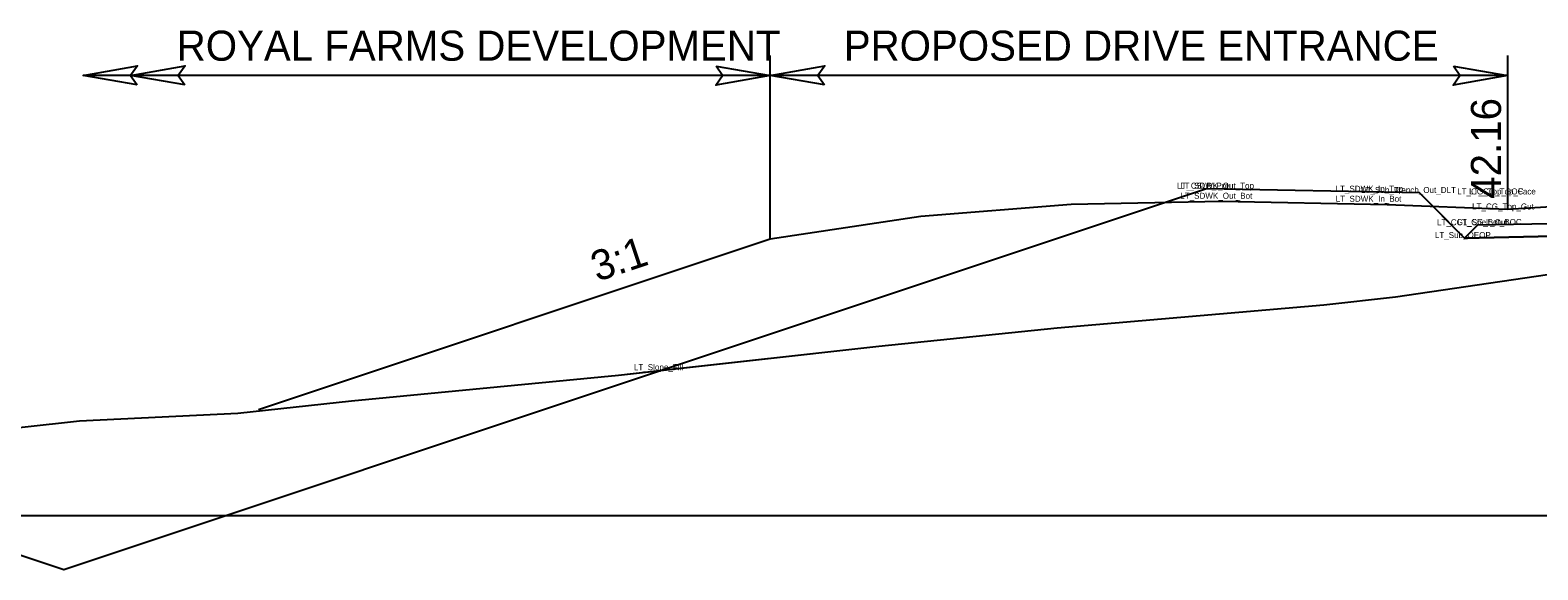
# Model space of a CAD drawing. Extents: x -26 to 2192773, y -11 to 86971.
# Drawn here: x 118.9 to 169, y 1998.2 to 2016.1 of the extents above; entities that cross this region are included whole.
import ezdxf

# ---------------------------------------------------------------- set-up
doc = ezdxf.new("R2010")
doc.units = 0
for name, color, linetype in [('Exist Cross Section Cell', 7, 'Continuous'), ('Exist XS Ground Line', 7, 'Continuous'), ('Old_Level_62', 7, 'Continuous'), ('Prop CMT Conc Surface', 7, 'Continuous'), ('Prop CMT Concrete Structures', 7, 'Continuous'), ('Prop CMT Pvmt Course 1 CG', 7, 'Continuous'), ('Prop CMT Slope Grass', 7, 'Continuous'), ('Prop CMT Subgrade Earthwork', 7, 'Continuous'), ('Prop Terminator CELL', 7, 'Continuous'), ('Prop XS Earthwork Shape', 7, 'Continuous'), ('Prop XS Hydro Elevations', 7, 'Continuous'), ('Prop XS Side Slope Text', 7, 'Continuous'), ('Scratch_Level_0', 7, 'Continuous')]:
    doc.layers.add(name, color=color, linetype=linetype)

msp = doc.modelspace()

# ---------------------------------------------------------------- linework, layer by layer
at = {"layer": 'Exist Cross Section Cell'}
msp.add_line((0, 2000), (200, 2000), dxfattribs=at)
at = {"layer": 'Exist XS Ground Line'}
msp.add_lwpolyline([(113.015, 2002.312), (120.545, 2003.136), (125.814, 2003.397), (129.587, 2003.806), (138.461, 2004.659), (147.108, 2005.62), (153.036, 2006.229), (161.901, 2006.996), (164.278, 2007.261), (171.291, 2008.285)], dxfattribs=at)
at = {"layer": 'Old_Level_62'}
for p, q in [((143.5, 2009.178), (143.5, 2015.27)), ((168, 2015.27), (168, 2010.158)), ((143.5, 2014.612), (120.668, 2014.612)), ((168, 2014.612), (143.5, 2014.612))]:
    msp.add_line(p, q, dxfattribs=at)
at = {"layer": 'Prop CMT Conc Surface'}
msp.add_lwpolyline([(170, 2010.278), (168, 2010.158)], dxfattribs=at)
at = {"layer": 'Prop CMT Concrete Structures'}
msp.add_lwpolyline([(170, 2010.278), (168, 2010.158)], dxfattribs=at)
at = {"layer": 'Prop CMT Pvmt Course 1 CG'}
for points in [[(170, 2009.694), (167, 2009.634), (166.575, 2009.209)], [(166.575, 2009.209), (170, 2009.278)]]:
    msp.add_lwpolyline(points, dxfattribs=at)
at = {"layer": 'Prop CMT Slope Grass'}
for p, q in [((158.5, 2010.428), (153.5, 2010.328)), ((164, 2010.318), (158.5, 2010.428)), ((148.5, 2009.928), (143.5, 2009.178)), ((153.5, 2010.328), (148.5, 2009.928)), ((168, 2010.158), (164, 2010.318)), ((143.5, 2009.178), (126.493, 2003.509))]:
    msp.add_line(p, q, dxfattribs=at)
at = {"layer": 'Prop CMT Subgrade Earthwork'}
msp.add_lwpolyline([(170, 2009.278), (166.575, 2009.209), (165.527, 2010.256)], dxfattribs=at)
at = {"layer": 'Prop Terminator CELL'}
for points in [[(122.468, 2014.302), (120.668, 2014.612), (122.478, 2014.932), (122.248, 2014.612)], [(124.048, 2014.302), (122.248, 2014.612), (124.058, 2014.932), (123.828, 2014.612)], [(141.7, 2014.922), (143.5, 2014.612), (141.69, 2014.292), (141.92, 2014.612)], [(145.3, 2014.302), (143.5, 2014.612), (145.31, 2014.932), (145.08, 2014.612)], [(166.2, 2014.922), (168, 2014.612), (166.19, 2014.292), (166.42, 2014.612)]]:
    msp.add_lwpolyline(points, close=True, dxfattribs=at)
at = {"layer": 'Prop XS Earthwork Shape'}
for points in [[(153.036, 2006.229), (161.901, 2006.996), (164.278, 2007.261), (171.291, 2008.285), (173.949, 2008.487), (179.063, 2008.824), (170, 2009.278), (166.575, 2009.209), (165.078, 2010.706), (157.999, 2010.848), (139.922, 2004.822), (147.108, 2005.62)], [(138.461, 2004.659), (139.922, 2004.822), (120.026, 1998.19), (108.825, 2001.924), (113.015, 2002.312), (120.545, 2003.136), (125.814, 2003.397), (129.587, 2003.806)]]:
    msp.add_lwpolyline(points, close=True, dxfattribs=at)

# ---------------------------------------------------------------- texts
at = {"layer": 'Old_Level_62'}
for s, p in [('ROYAL FARMS DEVELOPMENT', (123.78, 2015.099)), ('PROPOSED DRIVE ENTRANCE', (145.945, 2015.099))]:
    msp.add_text(s, height=1, rotation=360, dxfattribs=at).set_placement(p)
at = {"layer": 'Prop XS Hydro Elevations'}
msp.add_text('42.16', height=1, rotation=90, dxfattribs=at).set_placement((167.784, 2010.514))
at = {"layer": 'Prop XS Side Slope Text'}
msp.add_text('3:1', height=1, rotation=18.4332, dxfattribs=at).set_placement((137.749, 2007.752))
at = {"layer": 'Scratch_Level_0'}
for s, p in [('LT_CSLP_Pnt', (157.016, 2010.848)), ('LT_SDWK_Out_Top', (157.123, 2010.848)), ('LT_SDWK_In_Top', (162.285, 2010.748)), ('LT_SDWK_Out_Bot', (157.126, 2010.514)), ('LT_SDWK_In_Bot', (162.288, 2010.414)), ('LT_Sub_Trench_Out_DLT', (163.135, 2010.706)), ('LT_CG_Top_BOC', (166.327, 2010.658)), ('LT_CG_Top_Face', (166.725, 2010.658)), ('LT_CG_Top_Gut', (166.824, 2010.158)), ('LT_CG1_Shelf_Out', (165.655, 2009.634)), ('LT_CG_Bot_BOC', (166.332, 2009.644)), ('LT_Sub_OEOP', (165.586, 2009.209)), ('LT_Slope_Fill', (138.971, 2004.821))]:
    msp.add_text(s, height=0.2, dxfattribs=at).set_placement(p)

doc.saveas('drawing.dxf')
